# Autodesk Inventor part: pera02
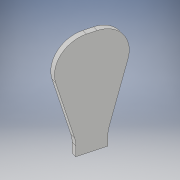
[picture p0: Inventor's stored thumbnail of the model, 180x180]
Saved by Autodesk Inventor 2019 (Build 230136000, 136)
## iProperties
Created: 2020-08
Part Number: pera02
Material: 一般
Document SubType Name: Modeling
Designer: kikut
Density: 1 g/cm^3
Appearance: 既定
Author: kikut
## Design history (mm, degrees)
sketch "スケッチ3"
  geometry: L1 (0.001, 0.01)-(-0.005, -0.009); L2 (-0.005, -0.009)-(-0.001, -0.01); L3 (-0.001, -0.01)-(0.005, 0.009); L4 (0.005, 0.009)-(0.001, 0.01); L5 (0.001, 0.01)-(-0.001, -0.01); L6 (-0.005, -0.009)-(0.005, 0.009); L7 (0, -0.014)-(0, 0.014) reference; 3 further points
  constraints: 12 end point, 3 midpoint, 2 parallel, 1 coincident, 1 perpendicular
  dimensions: "d8" = 0.02 distance of L1.start L1.end; "d9" = 165 deg angle of L7 L1; "d19" = 0.004 distance of L3.end L1.start
extrude "押し出し1" new body sketch "スケッチ3" distance "d10" = 0.079; taper "d11" = 0 deg
sketch "スケッチ6"
  geometry: L1 (-0.02, 0)-(-0.02, 0.079) reference; L2 (-0.02, 0.01)-(-0.04, 0.079); L3 (-0.04, 0.079)-(0.02, 0.079); L4 (0.02, 0.079)-(0, 0.01); L5 (0, 0)-(0, 0.079) reference; L6 (-0.02, 0.01)-(0, 0.01); L7 (-0.02, 0)-(0, 0) reference; 1 further point
  constraints: 8 end point, 2 perpendicular, 2 point on line
  dimensions: "d20" = 0.01 distance between parallel lines of L6 L7; "d21" = 0.06 distance of L2.end L3.end; "d22" = 0.02 distance from line of L2.end L1
extrude "押し出し3" join sketch "スケッチ6" distance "d23" = 0.004; taper "d24" = 0 deg
fillet "フィレット2" dims "d25" = 0.02
fillet "フィレット3" dims "d26" = 0.02
node "ソリッド1"
